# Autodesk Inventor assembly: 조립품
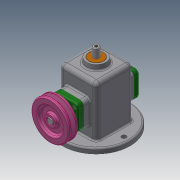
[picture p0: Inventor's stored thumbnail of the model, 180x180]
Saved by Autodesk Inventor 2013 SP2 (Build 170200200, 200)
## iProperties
Created: 2021-08
Part Number: 조립품
Document SubType Name: Assembly
Designer: kumcom13
Author: kumcom13
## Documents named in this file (16)
- C:\Users\kumcom13\Desktop\710806V1028\조립품.iam
- C:\Users\kumcom13\Desktop\710806V1028\본체.ipt
- C:\Users\kumcom13\Desktop\710806V1028\V벨트풀리.ipt
- C:\Users\kumcom13\Desktop\710806V1028\고정핀 1.2x8.ipt
- C:\Users\kumcom13\Desktop\710806V1028\뒤커버.ipt
- C:\Users\kumcom13\Desktop\710806V1028\링크.ipt
- C:\Users\kumcom13\Desktop\710806V1028\멈춤나사 M3x8.ipt
- C:\Users\kumcom13\Desktop\710806V1028\베어링 12x32x10.ipt
- C:\Users\kumcom13\Desktop\710806V1028\볼트 M4.ipt
- C:\Users\kumcom13\Desktop\710806V1028\부시.ipt
- C:\Users\kumcom13\Desktop\710806V1028\슬라이드.ipt
- C:\Users\kumcom13\Desktop\710806V1028\앞커버.ipt
- C:\Users\kumcom13\Desktop\710806V1028\오일 실 12 25 7.ipt
- C:\Users\kumcom13\Desktop\710806V1028\키 4x4x10.ipt
- C:\Users\kumcom13\Desktop\710806V1028\편심축.ipt
- C:\Users\kumcom13\Desktop\710806V1028\핀 5x18.ipt
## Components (3 placed, 3 different names)
1. V벨트풀리:1
2. 고정핀 1.2x8:1
3. 핀 5x18:1
